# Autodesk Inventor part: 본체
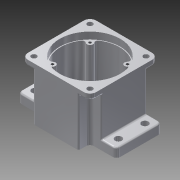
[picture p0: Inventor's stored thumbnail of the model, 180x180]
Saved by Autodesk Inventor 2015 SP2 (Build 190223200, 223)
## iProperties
Created: 2015-06
Part Number: 본체
Material: 알루미늄 6061
Document SubType Name: Modeling
Designer: AMC
Density: 2.7 g/cm^3
Appearance: 알루미늄 - 평지
Mass: 702.726 g
Surface Area: 674.763 cm^2
Volume: 260.269 cm^3
Author: AMC
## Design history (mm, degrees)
sketch "스케치1"
  geometry: L1 (-65, 30)-(65, 30); L2 (65, 30)-(65, -30); L3 (65, -30)-(-65, -30); L4 (-65, -30)-(-65, 30); L5 (-30, 45)-(30, 45); L6 (30, 45)-(30, -45); L7 (30, -45)-(-30, -45); L8 (-30, -45)-(-30, 45); 5 further points
  constraints: 16 end point, 4 midpoint, 4 parallel, 2 horizontal, 2 horizontal alignment, 2 perpendicular, 2 vertical alignment
  dimensions: "d0" = 90 distance between parallel lines of L7 L5; "d1" = 130 distance between parallel lines of L2 L4; "d2" = 60 distance between parallel lines of L6 L8; "d3" = 60 distance between parallel lines of L3 L1
extrude "돌출1" new body sketch "스케치1" distance "d4" = 12; taper "d5" = 0 deg
sketch "스케치2"
  geometry: L1 (-65, 30)-(-30, 30) reference; L2 (-30, 30)-(-30, 45) reference; L3 (-30, 45)-(30, 45) reference; L4 (30, 45)-(30, 30) reference; L5 (30, 30)-(65, 30) reference; L6 (65, 30)-(65, -30) reference; L7 (65, -30)-(30, -30) reference; L8 (30, -30)-(30, -45) reference; L9 (30, -45)-(-30, -45) reference; L10 (-30, -45)-(-30, -30) reference; L11 (-30, -30)-(-65, -30) reference; L12 (-65, -30)-(-65, 30) reference; L13 (-45, 45)-(45, 45); L14 (45, 45)-(45, -45); L15 (45, -45)-(-45, -45); L16 (-45, -45)-(-45, 45); 3 further points
  constraints: 8 end point, 2 midpoint, 2 parallel, 1 horizontal, 1 horizontal alignment, 1 perpendicular, 1 vertical alignment
  dimensions: "d6" = 90 distance between parallel lines of L13 L15; "d7" = 90 distance between parallel lines of L16 L14
extrude "돌출2" join sketch "스케치2" distance "d8" = 58; taper "d9" = 0 deg
sketch "스케치3"
  geometry: L1 (45, 45)-(45, 30) reference; L2 (30, 30)-(45, 30) reference; L3 (30, 45)-(30, 30) reference; L4 (-30, 45)-(30, 45) reference; L5 (-30, 30)-(-30, 45) reference; L6 (-45, 30)-(-30, 30) reference; L7 (-45, -30)-(-45, 30) reference; L8 (-45, -30)-(-65, -30) reference; L9 (-65, -30)-(-65, 30) reference; L10 (-65, 30)-(-45, 30) reference; L11 (-45, 30)-(-45, 45) reference; L12 (-45, 45)-(-30, 45) reference; L13 (30, 45)-(45, 45) reference; L14 (45, 30)-(45, -30) reference; L15 (65, -30)-(45, -30) reference; L16 (65, 30)-(65, -30) reference; L17 (45, 30)-(65, 30) reference; L18 (-45, -45)-(-45, -30) reference; L19 (-30, -30)-(-45, -30) reference; L20 (-30, -45)-(-30, -30) reference; L21 (-30, -45)-(-45, -45) reference; L22 (45, -30)-(45, -45) reference; L23 (45, -45)-(30, -45) reference; L24 (30, -45)-(-30, -45) reference; L25 (45, -30)-(30, -30) reference; L26 (30, -30)-(30, -45) reference; 1 further point
extrude "돌출3" cut sketch "스케치3" stored distance "d10" = 58; taper "d11" = 0 deg
sketch "스케치4"
  geometry: L1 (-45, -30)-(-45, 30) reference; L2 (-45, 30)-(-30, 30) reference; L3 (-30, 30)-(-30, 45) reference; L4 (-30, 45)-(30, 45) reference; L5 (30, 45)-(30, 30) reference; L6 (30, 30)-(45, 30) reference; L7 (45, 30)-(45, -30) reference; L8 (45, -30)-(30, -30) reference; L9 (30, -30)-(30, -45) reference; L10 (30, -45)-(-30, -45) reference; L11 (-30, -45)-(-30, -30) reference; L12 (-30, -30)-(-45, -30) reference; L13 (-45, 45)-(45, 45); L14 (45, 45)-(45, -45); L15 (45, -45)-(-45, -45); L16 (-45, -45)-(-45, 45); L17 (45, -30)-(45, 30) reference; 5 further points
  constraints: 8 end point, 8 midpoint, 2 parallel, 1 horizontal, 1 perpendicular
extrude "돌출4" join sketch "스케치4" distance "d12" = 7; taper "d13" = 0 deg
sketch "스케치5"
  geometry: L1 (-45, 45)-(45, 45) reference; L2 (45, 45)-(45, -45) reference; L3 (45, -45)-(-45, -45) reference; L4 (-45, -45)-(-45, 45) reference; C1 r 40 at (0, 0); 1 further point
  constraints: 1 centre point, 1 coincident
  dimensions: "d14" = 80 diameter of C1
extrude "돌출5" cut sketch "스케치5" distance "d15" = 9; taper "d16" = 0 deg
sketch "스케치6"
  geometry: C1 r 39 at (0, 0); 1 further point
  constraints: 1 centre point, 1 coincident
  dimensions: "d17" = 78 diameter of C1
extrude "돌출6" cut sketch "스케치6" distance "d18" = 52; taper "d19" = 0 deg
sketch "스케치7"
  geometry: C1 r 20.5 at (0, 11); C2 r 14 at (0, -20); 1 further point
  constraints: 2 centre point, 2 vertical alignment
  dimensions: "d20" = 41 diameter of C1; "d21" = 11 distance of point (0, 0) C1.centre; "d22" = 20 distance of point (0, 0) C2.centre; "d23" = 28 diameter of C2
extrude "돌출7" join sketch "스케치7" distance "d24" = 7; taper "d25" = 0 deg
sketch "스케치8"
  geometry: L1 (45, 30)-(45, -30) reference; L2 (45, -30)-(30, -30) reference; L3 (30, -30)-(30, -45) reference; L4 (30, -45)-(-30, -45) reference; L5 (-30, -45)-(-30, -30) reference; L6 (-30, -30)-(-45, -30) reference; L7 (-45, -30)-(-45, 30) reference; L8 (-45, 30)-(-30, 30) reference; L9 (-30, 30)-(-30, 45) reference; L10 (-30, 45)-(30, 45) reference; L11 (30, 45)-(30, 30) reference; L12 (30, 30)-(45, 30) reference; C1 r 39 at (0, 0) reference; C2 r 17.5 at (0, 11); A1 r 20.5 centre (0, 11) between (7.402, -8.117) and (-7.402, -8.117) reference; A2 r 14 centre (0, -20) between (-7.402, -8.117) and (7.402, -8.117) reference; 1 further point
  constraints: 1 centre point, 1 coincident
  dimensions: "d26" = 35 diameter of C2
extrude "돌출8" cut sketch "스케치8" distance "d27" = 10; taper "d28" = 0 deg
sketch "스케치9"
  geometry: L1 (-65, 19)-(-30, 19) reference; L2 (-30, 19)-(-30, 34) reference; L3 (-30, 34)-(30, 34) reference; L4 (30, 34)-(30, 19) reference; L5 (30, 19)-(65, 19) reference; L6 (65, 19)-(65, -41) reference; L7 (65, -41)-(30, -41) reference; L8 (30, -41)-(30, -56) reference; L9 (30, -56)-(-30, -56) reference; L10 (-30, -56)-(-30, -41) reference; L11 (-30, -41)-(-65, -41) reference; L12 (-65, -41)-(-65, 19) reference; C1 r 17.5 at (0, 0) reference; C2 r 12.5 at (0, 0); 1 further point
  constraints: 1 centre point, 1 coincident
  dimensions: "d29" = 25 diameter of C2
extrude "돌출9" cut sketch "스케치9" distance "d30" = 5; taper "d31" = 0 deg
sketch "스케치10"
  geometry: L1 (-65, 19)-(-30, 19) reference; L2 (-30, 19)-(-30, 34) reference; L3 (-30, 34)-(30, 34) reference; L4 (30, 34)-(30, 19) reference; L5 (30, 19)-(65, 19) reference; L6 (65, 19)-(65, -41) reference; L7 (65, -41)-(30, -41) reference; L8 (30, -41)-(30, -56) reference; L9 (30, -56)-(-30, -56) reference; L10 (-30, -56)-(-30, -41) reference; L11 (-30, -41)-(-65, -41) reference; L12 (-65, -41)-(-65, 19) reference; C1 r 12.5 at (0, 0) reference; C2 r 16 at (0, 0); 1 further point
  constraints: 1 centre point, 1 coincident
  dimensions: "d32" = 32 diameter of C2
extrude "돌출10" cut sketch "스케치10" distance "d33" = 7; taper "d34" = 0 deg
sketch "스케치11"
  geometry: L1 (30, 30)-(65, 30) reference; L2 (65, 30)-(65, -30) reference; L3 (65, -30)-(30, -30) reference; L4 (30, -30)-(30, -45) reference; L5 (30, -45)-(-30, -45) reference; L6 (-30, -45)-(-30, -30) reference; L7 (-30, -30)-(-65, -30) reference; L8 (-65, -30)-(-65, 30) reference; L9 (-65, 30)-(-30, 30) reference; L10 (-30, 30)-(-30, 45) reference; L11 (-30, 45)-(30, 45) reference; L12 (30, 45)-(30, 30) reference; C1 r 16 at (0, 11) reference; C2 r 25 at (0, 11); 1 further point
  constraints: 1 centre point, 1 coincident
  dimensions: "d35" = 50 diameter of C2
extrude "돌출11" join sketch "스케치11" distance "d36" = 7; taper "d37" = 0 deg
sketch "스케치12"
  geometry: L1 (45, 30)-(45, -30) reference; L2 (45, -30)-(30, -30) reference; L3 (30, -30)-(30, -45) reference; L4 (30, -45)-(-30, -45) reference; L5 (-30, -45)-(-30, -30) reference; L6 (-30, -30)-(-45, -30) reference; L7 (-45, -30)-(-45, 30) reference; L8 (-45, 30)-(-30, 30) reference; L9 (-30, 30)-(-30, 45) reference; L10 (-30, 45)-(30, 45) reference; L11 (30, 45)-(30, 30) reference; L12 (30, 30)-(45, 30) reference; C1 r 17.5 at (0, 11) reference; C2 r 39 at (0, 0) reference; C3 r 11 at (0, -20); A1 r 20.5 centre (0, 11) between (7.402, -8.117) and (-7.402, -8.117) reference; A2 r 14 centre (0, -20) between (-7.402, -8.117) and (7.402, -8.117) reference; 1 further point
  constraints: 1 centre point, 1 coincident
  dimensions: "d38" = 22 diameter of C3
extrude "돌출12" cut sketch "스케치12" distance "d39" = 7; taper "d40" = 0 deg
sketch "스케치13" dims "d12" = 7, "d13" = 0
  geometry: L1 (-65, 50)-(-30, 50) reference; L2 (-30, 50)-(-30, 65) reference; L3 (-30, 65)-(30, 65) reference; L4 (30, 65)-(30, 50) reference; L5 (30, 50)-(65, 50) reference; L6 (65, 50)-(65, -10) reference; L7 (65, -10)-(30, -10) reference; L8 (30, -10)-(30, -25) reference; L9 (30, -25)-(-30, -25) reference; L10 (-30, -25)-(-30, -10) reference; L11 (-30, -10)-(-65, -10) reference; L12 (-65, -10)-(-65, 50) reference; C1 r 11 at (0, 0) reference; C2 r 17.5 at (0, 31) reference; C3 r 39 at (0, 20) reference; C4 r 9.5 at (0, 0); A1 r 20.5 centre (0, 31) between (7.402, 11.883) and (-7.402, 11.883) reference; A2 r 14 centre (0, 0) between (-7.402, 11.883) and (7.402, 11.883) reference; 1 further point
  constraints: 1 centre point, 1 coincident
  dimensions: "d41" = 19 diameter of C4
extrude "돌출13" cut sketch "스케치13" distance "d42" = 1; taper "d43" = 0 deg
fillet "모깎기1" dims "d44" = 2
fillet "모깎기2" dims "d45" = 0.3
chamfer "모따기1" distance "d46" = 1; stored, may be unused: second distance "d47" = 2, angle "d48" = 45 deg
fillet "모깎기3" dims "d49" = 2
fillet "모깎기4" dims "d50" = 3
fillet "모깎기5" dims "d51" = 2
sketch "스케치14"
  geometry: L1 (45, 30)-(45, -30) reference; L2 (45, -30)-(30, -30) reference; L3 (30, -30)-(30, -45) reference; L4 (30, -45)-(-30, -45) reference; L5 (-30, -45)-(-30, -30) reference; L6 (-30, -30)-(-45, -30) reference; L7 (-45, -30)-(-45, 30) reference; L8 (-45, 30)-(-30, 30) reference; L9 (-30, 30)-(-30, 45) reference; L10 (-30, 45)-(30, 45) reference; L11 (30, 45)-(30, 30) reference; L12 (30, 30)-(45, 30) reference; L13 (0, 0)-(24.749, 24.749); L14 (0, 0)-(35, 0); L15 (21.92, 27.577)-(24.603, 30.26); L16 (18.811, 24.468)-(38.695, 24.468); L17 (23.31, 17.653)-(64.279, 17.653); L18 (27.577, 21.92)-(30.26, 24.603); C1 r 40 at (0, 0) reference; A1 r 39 centre (0, 0) between (24.603, 30.26) and (30.26, 24.603) reference; A2 r 4 centre (24.749, 24.749) between (21.92, 27.577) and (27.577, 21.92); 1 further point
  constraints: 12 end point, 4 point on circle, 3 horizontal, 2 tangent, 1 centre point, 1 coincident, 1 equal length
  dimensions: "d53" = 35 distance of L13.start L13.end; "d54" = 45 deg angle of L14 L13; "d55" = 8 diameter of A2; "d56" = 45 deg angle of L16 L15; "d58" = 45 deg angle of L17 L18
extrude "돌출14" join sketch "스케치14" stored distance "d59" = 1; taper "d60" = 0 deg
fillet "모깎기6" dims "d61" = 3.5
fillet "모깎기7" dims "d65" = 2
sketch "스케치15"
  geometry: L1 (45, 30)-(45, -30) reference; L2 (45, -30)-(30, -30) reference; L3 (30, -30)-(30, -45) reference; L4 (30, -45)-(-30, -45) reference; L5 (-30, -45)-(-30, -30) reference; L6 (-30, -30)-(-45, -30) reference; L7 (-45, -30)-(-45, 30) reference; L8 (-45, 30)-(-30, 30) reference; L9 (-30, 30)-(-30, 45) reference; L10 (-30, 45)-(30, 45) reference; L11 (30, 45)-(30, 30) reference; L12 (30, 30)-(45, 30) reference; C1 r 40 at (0, 0) reference; A1 r 3.5 centre (-19.238, -29.836) between (-21.809, -27.462) and (-21.134, -32.777) reference; A2 r 39 centre (0, 0) between (-21.134, -32.777) and (21.134, -32.777) reference; A3 r 3.5 centre (19.238, -29.836) between (21.134, -32.777) and (21.809, -27.462) reference; A4 r 4 centre (24.749, -24.749) between (27.462, -21.809) and (21.809, -27.462) reference; A5 r 3.5 centre (29.836, -19.238) between (27.462, -21.809) and (32.777, -21.134) reference; A6 r 39 centre (0, 0) between (32.777, -21.134) and (32.777, 21.134) reference; A7 r 3.5 centre (29.836, 19.238) between (32.777, 21.134) and (27.462, 21.809) reference; A8 r 4 centre (24.749, 24.749) between (21.809, 27.462) and (27.462, 21.809) reference; A9 r 3.5 centre (19.238, 29.836) between (21.809, 27.462) and (21.134, 32.777) reference; A10 r 39 centre (0, 0) between (21.134, 32.777) and (-21.134, 32.777) reference; A11 r 3.5 centre (-19.238, 29.836) between (-21.134, 32.777) and (-21.809, 27.462) reference; A12 r 4 centre (-24.749, 24.749) between (-27.462, 21.809) and (-21.809, 27.462) reference; A13 r 3.5 centre (-29.836, 19.238) between (-27.462, 21.809) and (-32.777, 21.134) reference; A14 r 39 centre (0, 0) between (-32.777, 21.134) and (-32.777, -21.134) reference; A15 r 3.5 centre (-29.836, -19.238) between (-32.777, -21.134) and (-27.462, -21.809) reference; A16 r 4 centre (-24.749, -24.749) between (-21.809, -27.462) and (-27.462, -21.809) reference; 1 further point
hole "구멍1" sketch "스케치15" at (-24.749, 24.749), (24.749, 24.749), (-24.749, -24.749), (24.749, -24.749) diameter "d66" = 3.459; stored, may be unused: countersink angle "d70" = 90 deg, drill point angle "d72" = 118 deg; dims "d67" = 12, "d68" = 4, "d69" = 2, "d71" = 15
fillet "모깎기8" dims "d73" = 5
fillet "모깎기9" dims "d74" = 5
fillet "모깎기10" dims "d75" = 2
sketch "스케치16"
  geometry: L1 (-60, 30)-(-43, 30) reference; L2 (-65, -25)-(-65, 25) reference; L3 (-43, -30)-(-60, -30) reference; L4 (-35, -30)-(-43, -30) reference; L5 (-30, -43)-(-30, -35) reference; L6 (28, -45)-(-28, -45) reference; L7 (30, -35)-(30, -43) reference; L8 (43, -30)-(35, -30) reference; L9 (45, 28)-(45, -28) reference; L10 (43, 30)-(60, 30) reference; L11 (65, 25)-(65, -25) reference; L12 (60, -30)-(43, -30) reference; L13 (-45, -28)-(-45, 28) reference; L14 (-43, 30)-(-35, 30) reference; L15 (-30, 35)-(-30, 43) reference; L16 (-28, 45)-(28, 45) reference; L17 (30, 43)-(30, 35) reference; L18 (35, 30)-(43, 30) reference; C1 r 11 at (0, -20) reference; C2 r 17.5 at (0, 11) reference; C3 r 4.5 at (-55, 17.5); A1 r 2 centre (-43, 28) between (-43, 30) and (-45, 28) reference; A2 r 5 centre (-60, 25) between (-60, 30) and (-65, 25) reference; A3 r 5 centre (-60, -25) between (-65, -25) and (-60, -30) reference; A4 r 5 centre (-35, -35) between (-30, -35) and (-35, -30) reference; A5 r 2 centre (-28, -43) between (-30, -43) and (-28, -45) reference; A6 r 2 centre (28, -43) between (28, -45) and (30, -43) reference; A7 r 5 centre (35, -35) between (35, -30) and (30, -35) reference; A8 r 2 centre (43, -28) between (43, -30) and (45, -28) reference; A9 r 2 centre (43, 28) between (45, 28) and (43, 30) reference; A10 r 5 centre (60, 25) between (65, 25) and (60, 30) reference; A11 r 5 centre (60, -25) between (60, -30) and (65, -25) reference; A12 r 2 centre (-43, -28) between (-45, -28) and (-43, -30) reference; A13 r 5 centre (-35, 35) between (-35, 30) and (-30, 35) reference; A14 r 2 centre (-28, 43) between (-28, 45) and (-30, 43) reference; A15 r 2 centre (28, 43) between (30, 43) and (28, 45) reference; A16 r 5 centre (35, 35) between (30, 35) and (35, 30) reference; A17 r 3.5 centre (-19.238, -29.836) between (-21.809, -27.462) and (-21.134, -32.777) reference; A18 r 39 centre (0, 0) between (-21.134, -32.777) and (21.134, -32.777) reference; A19 r 3.5 centre (19.238, -29.836) between (21.134, -32.777) and (21.809, -27.462) reference; A20 r 4 centre (24.749, -24.749) between (27.462, -21.809) and (21.809, -27.462) reference; A21 r 3.5 centre (29.836, -19.238) between (27.462, -21.809) and (32.777, -21.134) reference; A22 r 39 centre (0, 0) between (32.777, -21.134) and (32.777, 21.134) reference; A23 r 3.5 centre (29.836, 19.238) between (32.777, 21.134) and (27.462, 21.809) reference; A24 r 4 centre (24.749, 24.749) between (21.809, 27.462) and (27.462, 21.809) reference; A25 r 3.5 centre (19.238, 29.836) between (21.809, 27.462) and (21.134, 32.777) reference; A26 r 39 centre (0, 0) between (21.134, 32.777) and (-21.134, 32.777) reference; A27 r 3.5 centre (-19.238, 29.836) between (-21.134, 32.777) and (-21.809, 27.462) reference; A28 r 4 centre (-24.749, 24.749) between (-27.462, 21.809) and (-21.809, 27.462) reference; A29 r 3.5 centre (-29.836, 19.238) between (-27.462, 21.809) and (-32.777, 21.134) reference; A30 r 39 centre (0, 0) between (-32.777, 21.134) and (-32.777, -21.134) reference; A31 r 3.5 centre (-29.836, -19.238) between (-32.777, -21.134) and (-27.462, -21.809) reference; A32 r 4 centre (-24.749, -24.749) between (-21.809, -27.462) and (-27.462, -21.809) reference; A33 r 20.5 centre (0, 11) between (11.115, -6.225) and (-11.115, -6.225) reference; A34 r 3 centre (12.742, -8.746) between (11.115, -6.225) and (10.493, -10.732) reference; A35 r 14 centre (0, -20) between (-10.493, -10.732) and (10.493, -10.732) reference; A36 r 3 centre (-12.742, -8.746) between (-10.493, -10.732) and (-11.115, -6.225) reference
  constraints: 1 centre point
  dimensions: "d82" = 10 distance from line of L2 C3.centre; "d83" = 12.5 distance from line of L1 C3.centre; "d84" = 9 diameter of C3
extrude "돌출15" cut sketch "스케치16" stored distance "d85" = 1; taper "d86" = 0 deg
fillet "모깎기11" dims "d87" = 2
fillet "모깎기12" dims "d88" = 8
hole "구멍2" diameter "d91" = 7; stored, may be unused: countersink angle "d95" = 90 deg, drill point angle "d97" = 118 deg; dims "d89" = 10, "d90" = 10, "d92" = 8, "d93" = 4, "d94" = 2, "d96" = 15
sketch "스케치17"
  geometry: L1 (-60, 30)-(-35, 30) reference; L2 (-30, 35)-(-30, 43) reference; L3 (-28, 45)-(28, 45) reference; L4 (30, 43)-(30, 35) reference; L5 (35, 30)-(60, 30) reference; L6 (65, 25)-(65, -25) reference; L7 (60, -30)-(35, -30) reference; L8 (30, -35)-(30, -43) reference; L9 (28, -45)-(-28, -45) reference; L10 (-30, -43)-(-30, -35) reference; L11 (-35, -30)-(-60, -30) reference; L12 (-65, -25)-(-65, 25) reference; C1 r 4.5 at (-55, -17.5) reference; C2 r 4.5 at (-55, 17.5) reference; C3 r 4.5 at (55, -17.5) reference; C4 r 4.5 at (55, 17.5) reference; C5 r 27 at (0, 11) reference; C6 r 16 at (0, 11) reference; A1 r 5 centre (-35, 35) between (-35, 30) and (-30, 35) reference; A2 r 2 centre (-28, 43) between (-28, 45) and (-30, 43) reference; A3 r 2 centre (28, 43) between (30, 43) and (28, 45) reference; A4 r 5 centre (35, 35) between (30, 35) and (35, 30) reference; A5 r 5 centre (60, 25) between (65, 25) and (60, 30) reference; A6 r 5 centre (60, -25) between (60, -30) and (65, -25) reference; A7 r 5 centre (35, -35) between (35, -30) and (30, -35) reference; A8 r 2 centre (28, -43) between (28, -45) and (30, -43) reference; A9 r 2 centre (-28, -43) between (-30, -43) and (-28, -45) reference; A10 r 5 centre (-35, -35) between (-30, -35) and (-35, -30) reference; A11 r 5 centre (-60, -25) between (-65, -25) and (-60, -30) reference; A12 r 5 centre (-60, 25) between (-60, 30) and (-65, 25) reference; 2 further points
  constraints: 1 vertical alignment, 1 other
  dimensions: "d98" = 15 distance from line of L9 point (0, -30)
feature "엠보싱1" sketch "스케치17" dims "d6" = 90, "d7" = 90, "d99" = 0.5, "d100" = 0
fillet "모깎기13" dims "d101" = 2
node "솔리드1"
pattern_circular "원형 패턴1" dims angle "d63" = 360 deg
mirror "대칭1"
mirror "대칭2"
mirror "대칭3"
mirror "대칭4"
node "절단 모서리 투영1"
node "절단 모서리 투영2"
node "절단 모서리 투영3"
node "절단 모서리 투영4"
node "절단 모서리 투영5"
node "절단 모서리 투영6"
node "절단 모서리 투영7"
node "절단 모서리 투영8"
node "절단 모서리 투영9"
node "절단 모서리 투영10"
node "절단 모서리 투영11"
node "절단 모서리 투영12"
node "절단 모서리 투영13"
node "절단 모서리 투영14"
other parameters: "d57" = 45 deg
